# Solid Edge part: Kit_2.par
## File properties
Dokumentum tartalom típus: 0
Last saved by: ahadarics
Revision: 76
Sűrűség: 0,000 kg/m^3
Pontosság: 0,990
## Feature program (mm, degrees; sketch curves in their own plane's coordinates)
base feature "unnamed BaseFeature 1"
sketch for "unnamed Hole 1" plane through (-19, 19, 5) normal (0, 0, -1) x-axis (0, -1, 0)
  hole centre (0, 0) bore radius 2.4585
hole "unnamed Hole 1" through
sketch for "unnamed Hole 2" plane through (-19, 19, 5) normal (0, 0, -1) x-axis (0, -1, 0)
  hole centre (38, 0) bore radius 2.4585
hole "unnamed Hole 2" through
sketch for "unnamed Hole 3" plane through (-19, 19, 5) normal (0, 0, -1) x-axis (0, -1, 0)
  hole centre (38, -38) bore radius 2.4585
hole "unnamed Hole 3" through
sketch for "unnamed Hole 4" plane through (-19, 19, 5) normal (0, 0, -1) x-axis (0, -1, 0)
  hole centre (0, -38) bore radius 2.4585
hole "unnamed Hole 4" through
pattern "unnamed Pattern 1" of "unnamed Hole 1", "unnamed Hole 2", "unnamed Hole 3", "unnamed Hole 4"
sketch for "Furat_5" plane through (-27.3367, 0, 7.25) normal (-0.999962, 0, -0.008727) x-axis (0, -1, 0)
  hole centre (0.0005, 0.7497) bore radius 4.283
hole "Furat_5" diameter 8.566 finite
thread "unnamed Thread 1"
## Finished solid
Body 1: solid body, 289 faces, 699 edges, 431 vertices, 4 internal voids.
  Faces by surface: plane 145, cylinder 71, swept 43, torus 20, cone 9, spline 1
  Edges by curve: line 415, circle 158, spline 102, curve on surface 12, ellipse 12
Bounding box of the edges (mm; curved faces can reach further): 54.800 x 54.800 x 14.500, from (-27.4, -27.4, 0) to (27.4, 27.4, 14.5).
Cylindrical faces by radius (mm): R0.2 x36, R0.519 x1, R2.4585 x4, R2.5402 x12, R2.6 x4, R3.75 x4, R3.85 x4, R4.283 x1, R4.5 x5
Conical faces (half-angle, radius in mm at the cone's reference point): 0.5 deg R6.75 x4, 45 deg R2.7085 x4, 45 deg R4.65 x1
Toroidal faces (ring radius, tube radius in mm): R2.9402 r0.4 x12, R3.55 r0.2 x8
Planar faces by outward normal: +x 12, +y 15, +z 1, -x 13, -y 14, -z 22, oblique 68
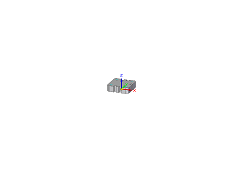
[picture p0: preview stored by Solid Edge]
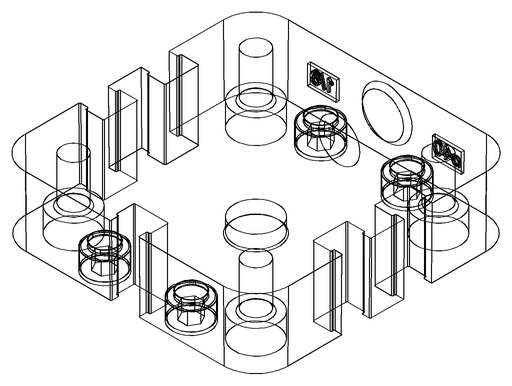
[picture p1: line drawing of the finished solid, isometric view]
